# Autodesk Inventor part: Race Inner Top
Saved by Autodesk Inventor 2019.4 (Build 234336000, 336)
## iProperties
Created: 2020-05
Part Number: Race Inner Top
Material: Generic
Document SubType Name: Modeling
Designer: Administrator
Density: 1 g/cm^3
Appearance: Default
Title: Race Inner Top
Author: Administrator
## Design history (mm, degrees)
feature "Race Inner Top"
body "Solid1"
